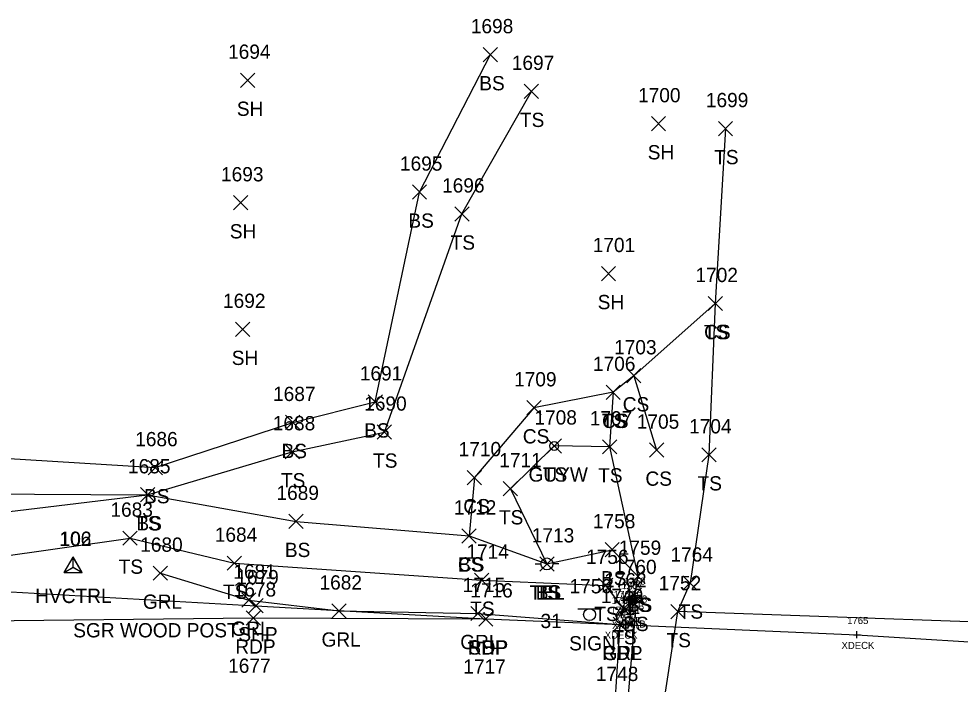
# Model space of a CAD drawing. Extents: x 1497084 to 1499861, y 734741 to 735567.
# Drawn here: x 1499429.7 to 1499561.5, y 735466.8 to 735560.1 of the extents above; entities that cross this region are included whole.
import ezdxf

# ---------------------------------------------------------------- set-up
doc = ezdxf.new("R2010")
doc.units = 0
for name, color, linetype in [('B_A', 7, 'Continuous'), ('B_I', 7, 'Continuous'), ('B_TIC', 7, 'Continuous'), ('BELB', 7, 'Continuous'), ('BSUBM', 7, 'Continuous'), ('C_A', 7, 'Continuous'), ('C_I', 7, 'Continuous'), ('CPSM', 7, 'Continuous'), ('L_A', 7, 'Continuous'), ('L_C', 7, 'Continuous'), ('L_I', 7, 'Continuous'), ('L_TIC', 7, 'Continuous'), ('LELB', 7, 'Continuous'), ('P_A', 7, 'Continuous'), ('P_I', 7, 'Continuous'), ('P_TIC', 7, 'Continuous'), ('PET', 7, 'Continuous'), ('PSP', 7, 'Continuous'), ('R_A', 7, 'Continuous'), ('R_C', 7, 'Continuous'), ('R_I', 7, 'Continuous'), ('R_TIC', 7, 'Continuous'), ('RGR', 7, 'Continuous'), ('S_A', 7, 'Continuous'), ('S_I', 7, 'Continuous'), ('SSGN', 7, 'Continuous'), ('U_A', 7, 'Continuous'), ('U_I', 7, 'Continuous'), ('UP', 7, 'Continuous'), ('UPGW', 7, 'Continuous')]:
    doc.layers.add(name, color=color, linetype=linetype)

msp = doc.modelspace()

# ---------------------------------------------------------------- linework, layer by layer
at = {"layer": 'B_TIC'}
for p, q in [((1499514.54, 735478.58), (1499514.62, 735478.58)), ((1499514.54, 735478.58), (1499514.62, 735478.58)), ((1499515.47, 735478.68), (1499515.55, 735478.68)), ((1499515.9, 735479.25), (1499515.98, 735479.25)), ((1499514.4, 735477.39), (1499514.48, 735477.39)), ((1499515.3, 735477.23), (1499515.37, 735477.23)), ((1499514.09, 735476.55), (1499514.16, 735476.55)), ((1499515.37, 735476.62), (1499515.44, 735476.62)), ((1499516.08, 735476.74), (1499516.16, 735476.74)), ((1499513.91, 735475.18), (1499513.99, 735475.18)), ((1499547.08, 735473.74), (1499547.16, 735473.74))]:
    msp.add_line(p, q, dxfattribs=at)
for points in [[(1499515.9, 735478.75), (1499515.9, 735479.75)], [(1499514.04, 735478.58), (1499515.04, 735478.58)], [(1499514.04, 735478.58), (1499515.04, 735478.58)], [(1499514.54, 735478.08), (1499514.54, 735479.08)], [(1499514.54, 735478.08), (1499514.54, 735479.08)], [(1499514.97, 735478.68), (1499515.97, 735478.68)], [(1499515.4, 735479.25), (1499516.4, 735479.25)], [(1499515.47, 735478.18), (1499515.47, 735479.18)], [(1499513.9, 735477.39), (1499514.9, 735477.39)], [(1499514.4, 735476.89), (1499514.4, 735477.89)], [(1499514.79, 735477.23), (1499515.79, 735477.23)], [(1499515.29, 735476.73), (1499515.29, 735477.73)], [(1499515.36, 735476.12), (1499515.36, 735477.12)], [(1499516.08, 735476.24), (1499516.08, 735477.24)], [(1499513.58, 735476.55), (1499514.58, 735476.55)], [(1499514.08, 735476.05), (1499514.08, 735477.05)], [(1499514.86, 735476.62), (1499515.86, 735476.62)], [(1499515.58, 735476.74), (1499516.58, 735476.74)], [(1499513.41, 735475.18), (1499514.41, 735475.18)], [(1499513.91, 735474.68), (1499513.91, 735475.68)], [(1499546.58, 735473.74), (1499547.58, 735473.74)], [(1499547.08, 735473.24), (1499547.08, 735474.24)]]:
    msp.add_lwpolyline(points, dxfattribs=at)
at = {"layer": 'BELB'}
msp.add_lwpolyline([(1499513.91, 735475.18), (1499547.08, 735473.74), (1499571.02, 735472.25), (1499596.08, 735469.99)], dxfattribs=at)
at = {"layer": 'BSUBM'}
for points in [[(1499512.91, 735449.28), (1499513.78, 735448.99), (1499513.83, 735450.64), (1499516.08, 735476.74), (1499515.9, 735479.25), (1499514.54, 735478.58)], [(1499515.36, 735476.62), (1499515.29, 735477.23), (1499515.47, 735478.68), (1499514.54, 735478.58), (1499514.4, 735477.39), (1499514.08, 735476.55)], [(1499514.08, 735476.55), (1499515.36, 735476.62)]]:
    msp.add_lwpolyline(points, dxfattribs=at)
at = {"layer": 'CPSM'}
for p, q in [((1499436.02, 735482.48), (1499437.27, 735484.65)), ((1499436.02, 735482.45), (1499437.27, 735484.62)), ((1499438.52, 735482.48), (1499437.27, 735484.65)), ((1499437.27, 735483.2), (1499437.27, 735484.65)), ((1499438.52, 735482.45), (1499437.27, 735484.62)), ((1499437.27, 735483.18), (1499437.27, 735484.62)), ((1499436.02, 735482.48), (1499437.27, 735483.2)), ((1499436.02, 735482.45), (1499437.27, 735483.18)), ((1499436.02, 735482.48), (1499438.52, 735482.48)), ((1499436.02, 735482.45), (1499438.52, 735482.45)), ((1499437.27, 735483.2), (1499437.27, 735483.2)), ((1499437.27, 735483.2), (1499438.52, 735482.48)), ((1499437.27, 735483.18), (1499437.27, 735483.18)), ((1499437.27, 735483.18), (1499438.52, 735482.45))]:
    msp.add_line(p, q, dxfattribs=at)
at = {"layer": 'L_TIC'}
for points in [[(1499494.73, 735554.05), (1499496.73, 735556.05)], [(1499496.73, 735554.05), (1499494.73, 735556.05)], [(1499460.72, 735550.47), (1499462.72, 735552.47)], [(1499462.72, 735550.47), (1499460.72, 735552.47)], [(1499500.47, 735548.91), (1499502.47, 735550.91)], [(1499502.47, 735548.91), (1499500.47, 735550.91)], [(1499518.28, 735544.37), (1499520.28, 735546.37)], [(1499520.28, 735544.37), (1499518.28, 735546.37)], [(1499527.67, 735543.69), (1499529.67, 735545.69)], [(1499529.67, 735543.69), (1499527.67, 735545.69)], [(1499484.8, 735534.79), (1499486.8, 735536.79)], [(1499486.8, 735534.79), (1499484.8, 735536.79)], [(1499459.73, 735533.29), (1499461.73, 735535.29)], [(1499461.73, 735533.29), (1499459.73, 735535.29)], [(1499490.75, 735531.72), (1499492.75, 735533.72)], [(1499492.75, 735531.72), (1499490.75, 735533.72)], [(1499511.28, 735523.37), (1499513.28, 735525.37)], [(1499513.28, 735523.37), (1499511.28, 735525.37)], [(1499526.23, 735519.17), (1499528.23, 735521.17)], [(1499528.23, 735519.17), (1499526.23, 735521.17)], [(1499526.23, 735519.17), (1499528.23, 735521.17)], [(1499528.23, 735519.17), (1499526.23, 735521.17)], [(1499460.01, 735515.55), (1499462.01, 735517.55)], [(1499462.01, 735515.55), (1499460.01, 735517.55)], [(1499514.83, 735509.04), (1499516.83, 735511.04)], [(1499516.83, 735509.04), (1499514.83, 735511.04)], [(1499514.83, 735509.04), (1499516.83, 735511.04)], [(1499516.83, 735509.04), (1499514.83, 735511.04)], [(1499511.93, 735506.72), (1499513.93, 735508.72)], [(1499513.93, 735506.72), (1499511.93, 735508.72)], [(1499511.93, 735506.72), (1499513.93, 735508.72)], [(1499513.93, 735506.72), (1499511.93, 735508.72)], [(1499478.61, 735505.38), (1499480.61, 735507.38)], [(1499480.61, 735505.38), (1499478.61, 735507.38)], [(1499500.83, 735504.55), (1499502.83, 735506.55)], [(1499502.83, 735504.55), (1499500.83, 735506.55)], [(1499467.03, 735502.5), (1499469.03, 735504.5)], [(1499469.03, 735502.5), (1499467.03, 735504.5)], [(1499479.88, 735501.15), (1499481.88, 735503.15)], [(1499481.88, 735501.15), (1499479.88, 735503.15)], [(1499503.67, 735499.2), (1499505.67, 735501.2)], [(1499505.67, 735499.2), (1499503.67, 735501.2)], [(1499511.43, 735499.08), (1499513.43, 735501.08)], [(1499513.43, 735499.08), (1499511.43, 735501.08)], [(1499511.43, 735499.08), (1499513.43, 735501.08)], [(1499513.43, 735499.08), (1499511.43, 735501.08)], [(1499466.98, 735498.39), (1499468.98, 735500.39)], [(1499468.98, 735498.39), (1499466.98, 735500.39)], [(1499518.01, 735498.62), (1499520.01, 735500.62)], [(1499520.01, 735498.62), (1499518.01, 735500.62)], [(1499525.34, 735497.96), (1499527.34, 735499.96)], [(1499527.34, 735497.96), (1499525.34, 735499.96)], [(1499447.77, 735496.16), (1499449.77, 735498.16)], [(1499449.77, 735496.16), (1499447.77, 735498.16)], [(1499492.49, 735494.76), (1499494.49, 735496.76)], [(1499494.49, 735494.76), (1499492.49, 735496.76)], [(1499446.7, 735492.36), (1499448.7, 735494.36)], [(1499448.7, 735492.36), (1499446.7, 735494.36)], [(1499446.7, 735492.36), (1499448.7, 735494.36)], [(1499448.7, 735492.36), (1499446.7, 735494.36)], [(1499497.53, 735493.2), (1499499.53, 735495.2)], [(1499499.53, 735493.2), (1499497.53, 735495.2)], [(1499467.5, 735488.63), (1499469.5, 735490.63)], [(1499469.5, 735488.63), (1499467.5, 735490.63)], [(1499444.24, 735486.28), (1499446.24, 735488.28)], [(1499446.24, 735486.28), (1499444.24, 735488.28)], [(1499491.74, 735486.59), (1499493.74, 735488.59)], [(1499493.74, 735486.59), (1499491.74, 735488.59)], [(1499491.74, 735486.59), (1499493.74, 735488.59)], [(1499493.74, 735486.59), (1499491.74, 735488.59)], [(1499511.79, 735484.66), (1499513.79, 735486.66)], [(1499513.79, 735484.66), (1499511.79, 735486.66)], [(1499458.87, 735482.77), (1499460.87, 735484.77)], [(1499460.87, 735482.77), (1499458.87, 735484.77)], [(1499502.65, 735482.67), (1499504.65, 735484.67)], [(1499504.65, 735482.67), (1499502.65, 735484.67)], [(1499502.65, 735482.67), (1499504.65, 735484.67)], [(1499504.65, 735482.67), (1499502.65, 735484.67)], [(1499493.5, 735480.39), (1499495.5, 735482.39)], [(1499495.5, 735480.39), (1499493.5, 735482.39)], [(1499515.41, 735480.94), (1499517.41, 735482.94)], [(1499517.41, 735480.94), (1499515.41, 735482.94)], [(1499515.41, 735480.94), (1499517.41, 735482.94)], [(1499517.41, 735480.94), (1499515.41, 735482.94)], [(1499510.88, 735479.66), (1499512.88, 735481.66)], [(1499512.88, 735479.66), (1499510.88, 735481.66)], [(1499522.7, 735479.99), (1499524.7, 735481.99)], [(1499524.7, 735479.99), (1499522.7, 735481.99)], [(1499522.7, 735479.99), (1499524.7, 735481.99)], [(1499524.7, 735479.99), (1499522.7, 735481.99)], [(1499514.9, 735478.25), (1499516.9, 735480.25)], [(1499516.9, 735478.25), (1499514.9, 735480.25)], [(1499513.4, 735476.39), (1499515.4, 735478.39)], [(1499515.4, 735476.39), (1499513.4, 735478.39)], [(1499521, 735475.98), (1499523, 735477.98)], [(1499523, 735475.98), (1499521, 735477.98)]]:
    msp.add_lwpolyline(points, dxfattribs=at)
at = {"layer": 'LELB'}
for points in [[(1498873.92, 735413.56), (1498885.61, 735419.45), (1498937.6, 735431.47), (1498992.42, 735446.17), (1499046.55, 735456.42), (1499100.05, 735466.4), (1499155.3, 735475.02), (1499211.81, 735485.81), (1499272.89, 735498.35), (1499312.63, 735498.22), (1499378.23, 735496.87), (1499423.72, 735498.7), (1499448.77, 735497.16), (1499468.03, 735503.5), (1499479.61, 735506.38), (1499485.8, 735535.79), (1499495.73, 735555.05)], [(1498887.06, 735413.08), (1498886.64, 735416.64), (1498937.22, 735426.43), (1498992.82, 735439.97), (1499047, 735450.43), (1499100.75, 735458.28), (1499155.76, 735466.18), (1499214.75, 735478.18), (1499272.85, 735494.27), (1499312.36, 735493.24), (1499378.42, 735492.78), (1499423.87, 735493.47), (1499447.7, 735493.36), (1499467.98, 735499.39), (1499480.88, 735502.15), (1499491.75, 735532.72), (1499501.47, 735549.91)], [(1499528.67, 735544.69), (1499527.23, 735520.17), (1499526.34, 735498.96), (1499523.7, 735480.99)], [(1499527.23, 735520.17), (1499515.83, 735510.04), (1499512.93, 735507.72), (1499501.83, 735505.55), (1499493.49, 735495.76), (1499492.74, 735487.59)], [(1499515.83, 735510.04), (1499519.01, 735499.62)], [(1499512.93, 735507.72), (1499512.43, 735500.08), (1499516.41, 735481.94)], [(1499512.43, 735500.08), (1499504.67, 735500.2), (1499498.53, 735494.2), (1499503.65, 735483.67)], [(1499315.72, 735484.63), (1499378.98, 735487.71), (1499425.23, 735490.63), (1499447.7, 735493.36), (1499468.5, 735489.63), (1499492.74, 735487.59), (1499503.65, 735483.67), (1499512.79, 735485.66), (1499516.41, 735481.94), (1499515.9, 735479.25)], [(1498836.02, 735409.82), (1498851.62, 735410.69), (1498873.71, 735408.53), (1498887.41, 735411.13), (1498937.88, 735419.58), (1498994.04, 735428.91), (1499054.48, 735438.88), (1499102.91, 735446.6), (1499157.52, 735455.49), (1499217.09, 735464.03), (1499265.79, 735469.16), (1499273.78, 735473.78), (1499316.12, 735477.44), (1499378.42, 735481.09), (1499425.85, 735484.53), (1499445.24, 735487.28), (1499459.87, 735483.77), (1499494.5, 735481.39), (1499511.88, 735480.66), (1499514.4, 735477.39)], [(1499517.61, 735404.27), (1499517.64, 735418.23), (1499516.71, 735431.72), (1499516.74, 735441.77), (1499518.27, 735446.31), (1499518.06, 735451.3), (1499522, 735476.98), (1499523.7, 735480.99)], [(1499585.16, 735474.77), (1499522, 735476.98)]]:
    msp.add_lwpolyline(points, dxfattribs=at)
at = {"layer": 'P_TIC'}
for points in [[(1499461.88, 735476.81), (1499463.88, 735478.81)], [(1499463.88, 735476.81), (1499461.88, 735478.81)], [(1499461.5, 735475.09), (1499463.5, 735477.09)], [(1499463.5, 735475.09), (1499461.5, 735477.09)], [(1499494.09, 735474.96), (1499496.09, 735476.96)], [(1499496.09, 735474.96), (1499494.09, 735476.96)], [(1499494.09, 735474.96), (1499496.09, 735476.96)], [(1499496.09, 735474.96), (1499494.09, 735476.96)], [(1499512.91, 735474.18), (1499514.91, 735476.18)], [(1499514.91, 735474.18), (1499512.91, 735476.18)], [(1499512.91, 735474.18), (1499514.91, 735476.18)], [(1499514.91, 735474.18), (1499512.91, 735476.18)]]:
    msp.add_lwpolyline(points, dxfattribs=at)
at = {"layer": 'PET'}
for points in [[(1498838.32, 735395.91), (1498888.99, 735404.3), (1498938.22, 735411.59), (1498994.69, 735421.68), (1499054.78, 735430.96), (1499104.38, 735439.6), (1499157.66, 735447.8), (1499219.31, 735457.47), (1499265.92, 735463.89), (1499317.31, 735469.95), (1499378.29, 735473.92), (1499424.75, 735475.7), (1499462.5, 735476.09), (1499495.09, 735475.96), (1499513.91, 735475.18)], [(1498842.44, 735373.21), (1498892.67, 735381.87), (1498940.26, 735389.17), (1498997.67, 735398.94), (1499056.44, 735408.41), (1499108.2, 735417.59), (1499160.18, 735425.34), (1499224.61, 735435.78), (1499269.11, 735441.52), (1499319.5, 735447.91), (1499378.39, 735452.04), (1499424.16, 735454.42), (1499461.26, 735454.74), (1499493.51, 735454.63), (1499512.44, 735453.4), (1499513.2, 735464.25), (1499513.91, 735475.18)]]:
    msp.add_lwpolyline(points, dxfattribs=at)
at = {"layer": 'PSP'}
msp.add_lwpolyline([(1498833.8, 735399.85), (1498855.6, 735403.69), (1498873.7, 735405.84), (1498888.17, 735408.98), (1498937.73, 735416.37), (1498993.87, 735425.67), (1499054.79, 735435.66), (1499103.37, 735443.86), (1499157.46, 735452.91), (1499218.03, 735462.22), (1499265.79, 735469.16), (1499316.87, 735474.83), (1499378.34, 735479.55), (1499425.23, 735479.95), (1499462.88, 735477.81), (1499495.09, 735475.96)], dxfattribs=at)
at = {"layer": 'R_TIC'}
for points in [[(1499448.5, 735481.37), (1499450.5, 735483.37)], [(1499450.5, 735481.37), (1499448.5, 735483.37)], [(1499460.89, 735477.59), (1499462.89, 735479.59)], [(1499462.89, 735477.59), (1499460.89, 735479.59)], [(1499473.53, 735476.07), (1499475.53, 735478.07)], [(1499475.53, 735476.07), (1499473.53, 735478.07)], [(1499492.97, 735475.72), (1499494.97, 735477.72)], [(1499494.97, 735475.72), (1499492.97, 735477.72)], [(1499512.91, 735474.18), (1499514.91, 735476.18)], [(1499514.91, 735474.18), (1499512.91, 735476.18)]]:
    msp.add_lwpolyline(points, dxfattribs=at)
at = {"layer": 'RGR'}
msp.add_lwpolyline([(1499449.5, 735482.37), (1499461.89, 735478.59), (1499474.53, 735477.07), (1499493.97, 735476.72), (1499513.91, 735475.18)], dxfattribs=at)
at = {"layer": 'SSGN'}
for p, q in [((1499507.98, 735477.39), (1499511.31, 735477.39)), ((1499509.62, 735476.56), (1499509.62, 735476.56))]:
    msp.add_line(p, q, dxfattribs=at)
msp.add_circle((1499509.62, 735476.56), 0.833, dxfattribs=at)
at = {"layer": 'UP'}
for p, q in [((1499501.99, 735483.67), (1499502.82, 735483.67)), ((1499503.65, 735483.67), (1499503.65, 735483.67)), ((1499505.32, 735483.67), (1499504.49, 735483.67)), ((1499504.49, 735483.67), (1499504.49, 735483.67)), ((1499505.32, 735483.67), (1499505.32, 735483.67))]:
    msp.add_line(p, q, dxfattribs=at)
msp.add_circle((1499503.65, 735483.67), 0.833, dxfattribs=at)
at = {"layer": 'UPGW'}
for radius in [0.625, 0.0833]:
    msp.add_circle((1499504.67, 735500.2), radius, dxfattribs=at)

# ---------------------------------------------------------------- texts
at = {"layer": 'B_A'}
for s, p in [('XAT', (1499513.24, 735476.58)), ('XAB', (1499513.26, 735476.58)), ('XAT', (1499514.18, 735476.68)), ('XAB', (1499514.62, 735477.25)), ('XAT', (1499513.11, 735475.39)), ('XAT', (1499514, 735475.23)), ('XAT', (1499512.79, 735474.55)), ('XAT', (1499514.07, 735474.62)), ('XAB', (1499514.8, 735474.74)), ('XDECK', (1499511.75, 735473.18)), ('XDECK', (1499544.92, 735471.74))]:
    msp.add_text(s, height=1, dxfattribs=at).set_placement(p)
at = {"layer": 'B_I'}
for s, p in [('1761', (1499513.45, 735480.08)), ('1761', (1499513.45, 735480.08)), ('1757', (1499514.12, 735480.18)), ('1760', (1499514.49, 735480.75)), ('1762', (1499513.03, 735478.89)), ('1755', (1499513.95, 735478.73)), ('1763', (1499512.71, 735478.05)), ('1754', (1499514.02, 735478.12)), ('1753', (1499514.73, 735478.24)), ('1749', (1499512.56, 735476.68)), ('1765', (1499545.71, 735475.24))]:
    msp.add_text(s, height=1, dxfattribs=at).set_placement(p)
at = {"layer": 'C_A'}
for p in [(1499431.96, 735478.2), (1499431.96, 735478.18)]:
    msp.add_text('HVCTRL', height=2, dxfattribs=at).set_placement(p)
at = {"layer": 'C_I'}
for s, p in [('106', (1499435.34, 735486.2)), ('102', (1499435.39, 735486.18))]:
    msp.add_text(s, height=2, dxfattribs=at).set_placement(p)
at = {"layer": 'L_A'}
for s, p in [('BS', (1499494.17, 735550.05)), ('SH', (1499460.21, 735546.47)), ('TS', (1499499.87, 735544.91)), ('SH', (1499517.77, 735540.37)), ('TS', (1499527.08, 735539.69)), ('BS', (1499484.24, 735530.79)), ('SH', (1499459.22, 735529.29)), ('TS', (1499490.16, 735527.72)), ('SH', (1499510.76, 735519.37)), ('TS', (1499525.64, 735515.17)), ('CS', (1499525.67, 735515.17)), ('SH', (1499459.49, 735511.55)), ('CS', (1499514.27, 735505.04)), ('CS', (1499514.27, 735505.04)), ('TS', (1499511.34, 735502.72)), ('CS', (1499511.37, 735502.72)), ('BS', (1499478.05, 735501.38)), ('CS', (1499500.27, 735500.55)), ('BS', (1499466.47, 735498.5)), ('TS', (1499479.29, 735497.15)), ('TS', (1499503.08, 735495.2)), ('TS', (1499510.83, 735495.08)), ('TS', (1499510.83, 735495.08)), ('TS', (1499466.39, 735494.39)), ('CS', (1499517.45, 735494.62)), ('TS', (1499524.75, 735493.96)), ('BS', (1499447.21, 735492.16)), ('CS', (1499491.93, 735490.76)), ('TS', (1499446.11, 735488.36)), ('BS', (1499446.14, 735488.36)), ('TS', (1499496.93, 735489.2)), ('BS', (1499466.94, 735484.63)), ('TS', (1499443.65, 735482.28)), ('CS', (1499491.18, 735482.59)), ('BS', (1499491.18, 735482.59)), ('BS', (1499511.23, 735480.66)), ('TS', (1499458.27, 735478.77)), ('TS', (1499502.06, 735478.67)), ('BS', (1499502.09, 735478.67)), ('TS', (1499492.91, 735476.39)), ('TS', (1499514.82, 735476.94)), ('BS', (1499514.85, 735476.94)), ('TS', (1499510.29, 735475.66)), ('TS', (1499522.11, 735475.99)), ('TS', (1499522.11, 735475.99)), ('BS', (1499514.34, 735474.25)), ('TS', (1499512.81, 735472.39)), ('TS', (1499520.41, 735471.98))]:
    msp.add_text(s, height=2, dxfattribs=at).set_placement(p)
at = {"layer": 'L_C'}
msp.add_text('31', height=2, dxfattribs=at).set_placement((1499502.75, 735474.67))
at = {"layer": 'L_I'}
for s, p in [('1698', (1499492.99, 735558.05)), ('1694', (1499458.98, 735554.47)), ('1697', (1499498.73, 735552.91)), ('1700', (1499516.42, 735548.37)), ('1699', (1499525.92, 735547.69)), ('1695', (1499483.06, 735538.79)), ('1693', (1499457.99, 735537.29)), ('1696', (1499488.96, 735535.72)), ('1701', (1499510.07, 735527.37)), ('1702', (1499524.46, 735523.17)), ('1702', (1499524.46, 735523.17)), ('1692', (1499458.27, 735519.55)), ('1703', (1499513.06, 735513.04)), ('1703', (1499513.06, 735513.04)), ('1706', (1499510.1, 735510.72)), ('1706', (1499510.1, 735510.72)), ('1691', (1499477.44, 735509.38)), ('1709', (1499499.05, 735508.55)), ('1687', (1499465.28, 735506.5)), ('1690', (1499478.05, 735505.15)), ('1708', (1499501.9, 735503.2)), ('1707', (1499509.65, 735503.08)), ('1707', (1499509.65, 735503.08)), ('1688', (1499465.24, 735502.39)), ('1705', (1499516.24, 735502.62)), ('1704', (1499523.57, 735501.96)), ('1686', (1499445.97, 735500.16)), ('1710', (1499491.28, 735498.76)), ('1685', (1499444.96, 735496.36)), ('1685', (1499444.96, 735496.36)), ('1711', (1499496.97, 735497.2)), ('1689', (1499465.76, 735492.63)), ('1683', (1499442.5, 735490.28)), ('1712', (1499490.61, 735490.59)), ('1712', (1499490.61, 735490.59)), ('1758', (1499510.09, 735488.66)), ('1684', (1499457.12, 735486.77)), ('1713', (1499501.53, 735486.67)), ('1713', (1499501.53, 735486.67)), ('1714', (1499492.37, 735484.39)), ('1759', (1499513.71, 735484.94)), ('1759', (1499513.71, 735484.94)), ('1756', (1499509.13, 735483.66)), ('1764', (1499520.96, 735483.99)), ('1764', (1499520.96, 735483.99)), ('1760', (1499513.07, 735482.25)), ('1762', (1499511.66, 735480.39)), ('1752', (1499519.31, 735479.98))]:
    msp.add_text(s, height=2, dxfattribs=at).set_placement(p)
at = {"layer": 'P_A'}
for s, p in [('SHP', (1499460.42, 735472.81)), ('RDP', (1499459.99, 735471.09)), ('SHP', (1499492.63, 735470.96)), ('RDP', (1499492.58, 735470.96)), ('RDP', (1499511.4, 735470.18)), ('RDP', (1499511.4, 735470.18))]:
    msp.add_text(s, height=2, dxfattribs=at).set_placement(p)
at = {"layer": 'P_I'}
for s, p in [('1679', (1499460.13, 735480.81)), ('1678', (1499459.76, 735479.09)), ('1716', (1499492.91, 735478.96)), ('1716', (1499492.91, 735478.96)), ('1749', (1499511.21, 735478.18)), ('1749', (1499511.21, 735478.18)), ('1677', (1499458.99, 735468.4)), ('1717', (1499491.93, 735468.28)), ('1748', (1499510.51, 735467.25)), ('1748', (1499510.51, 735467.25))]:
    msp.add_text(s, height=2, dxfattribs=at).set_placement(p)
at = {"layer": 'R_A'}
for p in [(1499447.04, 735477.37), (1499459.44, 735473.59), (1499472.07, 735472.07), (1499491.51, 735471.72), (1499511.45, 735470.18)]:
    msp.add_text('GRL', height=2, dxfattribs=at).set_placement(p)
at = {"layer": 'R_C'}
msp.add_text('SGR WOOD POST', height=2, dxfattribs=at).set_placement((1499437.29, 735473.37))
at = {"layer": 'R_I'}
for s, p in [('1680', (1499446.67, 735485.37)), ('1681', (1499459.72, 735481.59)), ('1682', (1499471.79, 735480.07)), ('1715', (1499491.84, 735479.72)), ('1749', (1499511.21, 735478.18))]:
    msp.add_text(s, height=2, dxfattribs=at).set_placement(p)
at = {"layer": 'S_A'}
msp.add_text('SIGN', height=2, dxfattribs=at).set_placement((1499506.76, 735471.54))
at = {"layer": 'S_I'}
msp.add_text('1750', height=2, dxfattribs=at).set_placement((1499506.82, 735479.54))
at = {"layer": 'U_A'}
for s, p in [('GUYW', (1499501.07, 735495.2)), ('TEL', (1499501.21, 735478.67))]:
    msp.add_text(s, height=2, dxfattribs=at).set_placement(p)
at = {"layer": 'U_I'}
for s, p in [('1708', (1499501.9, 735503.2)), ('1713', (1499501.53, 735486.67))]:
    msp.add_text(s, height=2, dxfattribs=at).set_placement(p)

doc.saveas('drawing.dxf')
